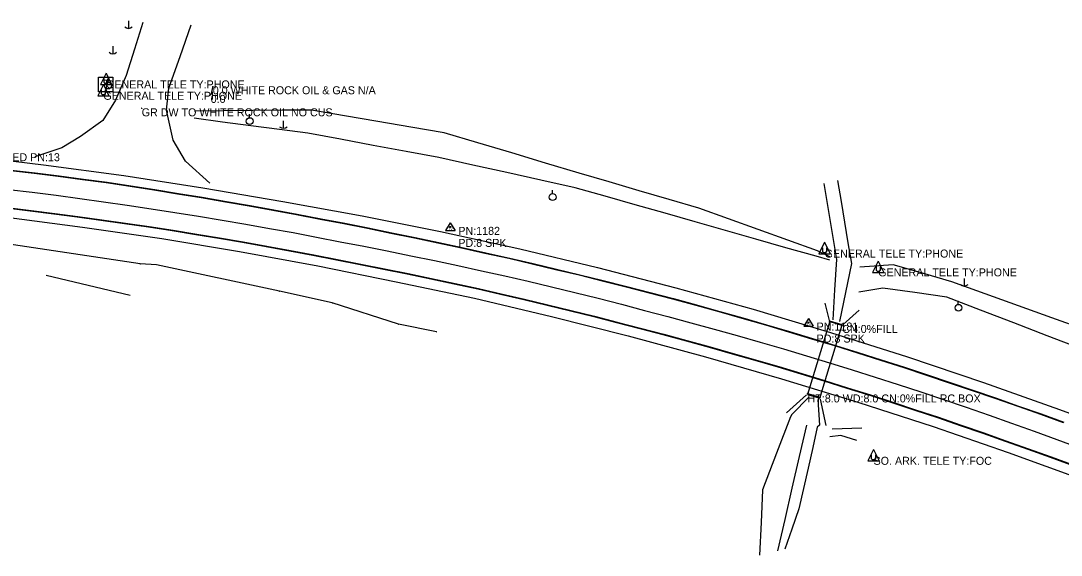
# Model space of a CAD drawing. Extents: x 878399 to 889864, y 1564003 to 1567413.
# Drawn here: x 882072 to 882722, y 1566924 to 1567257 of the extents above; entities that cross this region are included whole.
import ezdxf

# ---------------------------------------------------------------- set-up
doc = ezdxf.new("R2010")
doc.units = 0
for name, color, linetype in [('S_CROSS_DRAIN', 7, 'Continuous'), ('S_CROSS_DRAIN_ANNOT', 7, 'Continuous'), ('S_DITCHLINE', 7, 'Continuous'), ('S_DRG_PT_SYM', 7, 'Continuous'), ('S_DRIVEWAY', 7, 'Continuous'), ('S_EDGE_PAVEMENT', 7, 'Continuous'), ('S_FIBER_OPTIC_CABLE', 7, 'Continuous'), ('S_HEADWALL', 7, 'Continuous'), ('S_MSC_PT_SYM', 7, 'Continuous'), ('S_PAVEMENT_CROWN', 7, 'Continuous'), ('S_PRIMARY_CTL_ANNOT', 7, 'Continuous'), ('S_SECONDARY_CTL', 7, 'Continuous'), ('S_SECONDARY_CTL_ANNOT', 7, 'Continuous'), ('S_SHOULDER', 7, 'Continuous'), ('S_SIGN', 7, 'Continuous'), ('S_SIGN_ANNOT', 7, 'Continuous'), ('S_SURVEY_TEXT_ANNOT', 7, 'Continuous'), ('S_TELEPHONE_UTILITIES', 7, 'Continuous'), ('S_UTILITY_POLE', 7, 'Continuous'), ('S_UTILITY_POLE_ANNOT', 7, 'Continuous'), ('S_UTL_PT_SYM', 7, 'Continuous'), ('S_WALL', 7, 'Continuous')]:
    doc.layers.add(name, color=color, linetype=linetype)

msp = doc.modelspace()

# ---------------------------------------------------------------- linework, layer by layer
at = {"layer": 'S_CROSS_DRAIN'}
for p, q in [((882577.74, 1567069.92), (882563.77, 1567024.23)), ((882571.4, 1567021.9), (882585.44, 1567067.6)), ((882585.44, 1567067.6), (882577.74, 1567069.92)), ((882563.77, 1567024.23), (882571.4, 1567021.9))]:
    msp.add_line(p, q, dxfattribs=at)
at = {"layer": 'S_DITCHLINE'}
for points in [[(882577.64, 1567110.13), (882570.07, 1567113.96), (882551.53, 1567120.59), (882533, 1567127.23), (882514.46, 1567133.87), (882495.93, 1567140.5), (882477.24, 1567145.96), (882458.56, 1567151.41), (882439.87, 1567156.87), (882421.18, 1567162.33), (882400.06, 1567168.63), (882378.95, 1567174.94), (882357.83, 1567181.24), (882336.71, 1567187.55), (882315.99, 1567191.11), (882295.27, 1567194.66), (882274.55, 1567198.22), (882253.83, 1567201.78), (882235.56, 1567201.58), (882217.29, 1567201.38), (882199.02, 1567201.18), (882180.75, 1567200.98)], [(882577.71, 1567108.12), (882569.1, 1567110.44), (882550.22, 1567115.82), (882531.35, 1567121.2), (882512.47, 1567126.58), (882493.59, 1567131.96), (882474.82, 1567137.29), (882456.05, 1567142.63), (882437.28, 1567147.96), (882418.5, 1567153.29), (882397.24, 1567158), (882375.97, 1567162.7), (882354.71, 1567167.41), (882333.45, 1567172.12), (882312.98, 1567175.91), (882292.52, 1567179.71), (882272.05, 1567183.5), (882251.59, 1567187.29), (882233.85, 1567189.62), (882216.11, 1567191.95), (882198.38, 1567194.28), (882180.64, 1567196.61)], [(882579.77, 1567070.75), (882580.86, 1567089.59), (882581.95, 1567108.44), (882578.06, 1567132.14), (882574.17, 1567155.84)], [(882583.88, 1567069.68), (882587.64, 1567087.81), (882591.39, 1567105.93), (882589.21, 1567118.87), (882587.04, 1567131.82), (882584.86, 1567144.76), (882582.69, 1567157.7)], [(882737.26, 1567064.64), (882716.39, 1567072.13), (882695.52, 1567079.62), (882674.66, 1567087.11), (882653.79, 1567094.6), (882635.52, 1567099.84), (882617.25, 1567105.07), (882596.32, 1567103.69)], [(882140.71, 1567085.92), (882127.61, 1567089.06), (882114.5, 1567092.2), (882101.39, 1567095.34), (882088.28, 1567098.48)], [(882734.33, 1567052.82), (882713.46, 1567060.86), (882692.59, 1567068.89), (882671.72, 1567076.92), (882650.85, 1567084.95), (882630.79, 1567087.8), (882610.73, 1567090.64), (882595.71, 1567088.05)], [(882564.84, 1567022.71), (882553.84, 1567011.68), (882553.13, 1567010.32), (882544.37, 1566987.47), (882535.61, 1566964.61), (882534.7, 1566944.24), (882533.8, 1566923.88)], [(882570.18, 1567021.11), (882571.18, 1567005.13), (882569.84, 1567003.88), (882566.95, 1566991.09), (882564.06, 1566978.29), (882561.17, 1566965.5), (882558.28, 1566952.71), (882553.88, 1566940.2), (882549.48, 1566927.7)], [(882545.23, 1566926.51), (882549.73, 1566946.16), (882554.24, 1566965.81), (882558.75, 1566985.46), (882563.25, 1567005.12)], [(882597.6, 1567003.08), (882579.03, 1567002.61)], [(882594.52, 1566995.48), (882584.64, 1566998.54), (882577.69, 1566997.68)]]:
    msp.add_lwpolyline(points, dxfattribs=at)
at = {"layer": 'S_DRG_PT_SYM'}
for points in [[(882577.74, 1567069.92), (882577.74, 1567069.97), (882577.74, 1567069.92), (882577.69, 1567069.92), (882577.74, 1567069.92), (882577.74, 1567069.87), (882577.74, 1567069.92), (882577.79, 1567069.92)], [(882585.44, 1567067.6), (882585.44, 1567067.65), (882585.44, 1567067.6), (882585.39, 1567067.6), (882585.44, 1567067.6), (882585.44, 1567067.55), (882585.44, 1567067.6), (882585.49, 1567067.6)], [(882563.77, 1567024.23), (882563.77, 1567024.28), (882563.77, 1567024.23), (882563.72, 1567024.23), (882563.77, 1567024.23), (882563.77, 1567024.18), (882563.77, 1567024.23), (882563.82, 1567024.23)], [(882571.4, 1567021.9), (882571.4, 1567021.95), (882571.4, 1567021.9), (882571.35, 1567021.9), (882571.4, 1567021.9), (882571.4, 1567021.85), (882571.4, 1567021.9), (882571.45, 1567021.9)]]:
    msp.add_lwpolyline(points, dxfattribs=at)
at = {"layer": 'S_DRIVEWAY'}
for points in [[(882148.5, 1567256.43), (882143.36, 1567239.86), (882138.23, 1567223.29), (882131.55, 1567207.92), (882123.68, 1567195.31), (882109.64, 1567185.28), (882097.89, 1567178.24), (882081.07, 1567172.61)], [(882190.32, 1567156.11), (882175.28, 1567169.92), (882167.56, 1567182.95), (882163.27, 1567201.7), (882164.89, 1567215.46), (882171.82, 1567235.26), (882178.76, 1567255.05)]]:
    msp.add_lwpolyline(points, dxfattribs=at)
at = {"layer": 'S_EDGE_PAVEMENT'}
for points in [[(882065.86, 1567163.92), (882080.78, 1567162.37), (882080.78, 1567162.37), (882095.66, 1567160.52), (882110.88, 1567158.46), (882110.88, 1567158.46), (882125.75, 1567156.44), (882140.6, 1567154.31), (882140.6, 1567154.31), (882155.41, 1567151.91), (882170.22, 1567149.52), (882185.03, 1567147.12), (882185.03, 1567147.12), (882185.03, 1567147.12), (882200.21, 1567144.48), (882200.21, 1567144.48), (882214.99, 1567141.91), (882214.99, 1567141.91), (882214.99, 1567141.91), (882229.77, 1567139.33), (882229.77, 1567139.33), (882244.52, 1567136.58), (882259.39, 1567133.72), (882274.12, 1567130.88), (882274.12, 1567130.88), (882288.84, 1567127.97), (882288.84, 1567127.97), (882303.53, 1567124.94), (882318.22, 1567121.9), (882318.22, 1567121.9), (882318.22, 1567121.9), (882332.91, 1567118.86), (882332.91, 1567118.86), (882332.91, 1567118.86), (882347.57, 1567115.67), (882347.57, 1567115.67), (882362.23, 1567112.47), (882377.22, 1567109.2), (882377.22, 1567109.2), (882391.83, 1567105.79), (882391.83, 1567105.79), (882406.42, 1567102.29), (882421, 1567098.78), (882435.57, 1567095.2), (882435.57, 1567095.2), (882435.57, 1567095.2), (882450.38, 1567091.4), (882464.91, 1567087.67), (882479.45, 1567083.95), (882479.45, 1567083.95), (882479.45, 1567083.95), (882493.9, 1567079.92), (882508.35, 1567075.89), (882508.35, 1567075.89), (882508.35, 1567075.89), (882522.8, 1567071.85), (882522.8, 1567071.85), (882537.5, 1567067.57), (882551.88, 1567063.29), (882551.88, 1567063.29), (882566.25, 1567059.01), (882566.25, 1567059.01), (882566.25, 1567059.01), (882580.61, 1567054.67), (882594.93, 1567050.18), (882609.24, 1567045.69), (882623.85, 1567041.12), (882638.07, 1567036.34), (882652.28, 1567031.55), (882652.28, 1567031.55), (882666.5, 1567026.77), (882680.68, 1567021.86), (882695.03, 1567016.8), (882709.18, 1567011.82), (882723.31, 1567006.76)], [(882066.41, 1567164.12), (882081.33, 1567162.57), (882081.33, 1567162.57), (882096.22, 1567160.71), (882111.43, 1567158.65), (882111.43, 1567158.65), (882126.3, 1567156.64), (882141.15, 1567154.5), (882141.15, 1567154.5), (882155.96, 1567152.11), (882170.77, 1567149.71), (882185.58, 1567147.32), (882185.58, 1567147.32), (882185.58, 1567147.32), (882200.76, 1567144.68), (882200.76, 1567144.68), (882215.54, 1567142.1), (882215.54, 1567142.1), (882215.54, 1567142.1), (882230.32, 1567139.53), (882230.32, 1567139.53), (882245.06, 1567136.78), (882259.94, 1567133.91), (882274.67, 1567131.07), (882274.67, 1567131.07), (882289.38, 1567128.17), (882289.38, 1567128.17), (882304.07, 1567125.13), (882318.76, 1567122.1), (882318.76, 1567122.1), (882318.76, 1567122.1), (882333.45, 1567119.06), (882333.45, 1567119.06), (882333.45, 1567119.06), (882348.11, 1567115.86), (882348.11, 1567115.86), (882362.77, 1567112.67), (882377.76, 1567109.39), (882377.76, 1567109.39), (882392.37, 1567105.99), (882392.37, 1567105.99), (882406.96, 1567102.48), (882421.54, 1567098.98), (882436.11, 1567095.4), (882436.11, 1567095.4), (882436.11, 1567095.4), (882450.92, 1567091.6), (882465.45, 1567087.87), (882479.98, 1567084.14), (882479.98, 1567084.14), (882479.98, 1567084.14), (882494.43, 1567080.12), (882508.88, 1567076.09), (882508.88, 1567076.09), (882508.88, 1567076.09), (882523.33, 1567072.05), (882523.33, 1567072.05), (882538.03, 1567067.77), (882552.41, 1567063.49), (882552.41, 1567063.49), (882566.78, 1567059.21), (882566.78, 1567059.21), (882566.78, 1567059.21), (882581.14, 1567054.87), (882595.46, 1567050.38), (882609.77, 1567045.9), (882624.37, 1567041.32), (882638.59, 1567036.54), (882652.81, 1567031.76), (882652.81, 1567031.76), (882667.03, 1567026.97), (882681.2, 1567022.06), (882695.56, 1567017), (882709.71, 1567012.02), (882723.83, 1567006.96)], [(882063.3, 1567140.72), (882078.18, 1567138.83), (882093.06, 1567136.95), (882107.51, 1567135.12), (882122.37, 1567133.05), (882137.21, 1567130.92), (882137.21, 1567130.92), (882137.21, 1567130.92), (882152.06, 1567128.78), (882166.9, 1567126.53), (882181.7, 1567124.09), (882195.95, 1567121.74), (882210.75, 1567119.28), (882210.75, 1567119.28), (882225.51, 1567116.58), (882240.26, 1567113.87), (882254.84, 1567111.2), (882269.56, 1567108.32), (882284.27, 1567105.37), (882298.98, 1567102.42), (882298.98, 1567102.42), (882298.98, 1567102.42), (882313.68, 1567099.43), (882328.36, 1567096.36), (882343.04, 1567093.29), (882357.73, 1567090.21), (882371.89, 1567086.88), (882386.49, 1567083.45), (882401.1, 1567080.02), (882415.66, 1567076.44), (882415.66, 1567076.44), (882415.66, 1567076.44), (882430.21, 1567072.79), (882444.39, 1567069.23), (882458.92, 1567065.48), (882473.4, 1567061.56), (882487.88, 1567057.64), (882502.36, 1567053.71), (882516.77, 1567049.56), (882530.78, 1567045.52), (882545.2, 1567041.37), (882559.56, 1567037.04), (882573.9, 1567032.63), (882588.24, 1567028.23), (882602.55, 1567023.72), (882616.42, 1567019.16), (882630.67, 1567014.48), (882644.92, 1567009.79), (882659.1, 1567004.88), (882673.27, 1566999.97), (882687.17, 1566995.15), (882701.29, 1566990.09), (882715.39, 1566984.97), (882729.49, 1566979.85)], [(882063.85, 1567140.92), (882078.73, 1567139.03), (882093.62, 1567137.14), (882108.06, 1567135.31), (882122.92, 1567133.25), (882137.77, 1567131.11), (882137.77, 1567131.11), (882137.77, 1567131.11), (882152.61, 1567128.98), (882167.44, 1567126.73), (882182.25, 1567124.29), (882196.5, 1567121.94), (882211.3, 1567119.48), (882211.3, 1567119.48), (882226.06, 1567116.77), (882240.81, 1567114.07), (882255.38, 1567111.39), (882270.1, 1567108.51), (882284.81, 1567105.57), (882299.52, 1567102.62), (882299.52, 1567102.62), (882299.52, 1567102.62), (882314.22, 1567099.62), (882328.9, 1567096.56), (882343.59, 1567093.49), (882358.27, 1567090.41), (882372.43, 1567087.08), (882387.03, 1567083.65), (882401.63, 1567080.22), (882416.2, 1567076.64), (882416.2, 1567076.64), (882416.2, 1567076.64), (882430.75, 1567072.99), (882444.93, 1567069.43), (882459.45, 1567065.68), (882473.93, 1567061.76), (882488.41, 1567057.84), (882502.89, 1567053.91), (882517.31, 1567049.76), (882531.32, 1567045.72), (882545.73, 1567041.57), (882560.09, 1567037.24), (882574.43, 1567032.84), (882588.77, 1567028.43), (882603.08, 1567023.92), (882616.95, 1567019.37), (882631.2, 1567014.69), (882645.45, 1567009.99), (882659.62, 1567005.08), (882673.79, 1567000.17), (882687.7, 1566995.36), (882701.82, 1566990.3), (882715.92, 1566985.18), (882730.02, 1566980.06)]]:
    msp.add_lwpolyline(points, dxfattribs=at)
at = {"layer": 'S_FIBER_OPTIC_CABLE'}
for p, q in [((882146.98, 1567105.69), (882063.57, 1567118.17)), ((882157.14, 1567105.22), (882146.98, 1567105.69)), ((882233.84, 1567088.61), (882157.14, 1567105.22)), ((882266.92, 1567081.5), (882233.84, 1567088.61)), ((882308.36, 1567068.09), (882266.92, 1567081.5)), ((882332.06, 1567063.28), (882308.36, 1567068.09))]:
    msp.add_line(p, q, dxfattribs=at)
at = {"layer": 'S_HEADWALL'}
for points in [[(882585.82, 1567067.1), (882577.21, 1567069.77)], [(882572.05, 1567022.12), (882563.41, 1567024.82)]]:
    msp.add_lwpolyline(points, dxfattribs=at)
at = {"layer": 'S_MSC_PT_SYM'}
for points in [[(882190.96, 1567211.2), (882190.96, 1567211.25), (882190.96, 1567211.2), (882190.91, 1567211.2), (882190.96, 1567211.2), (882190.96, 1567211.15), (882190.96, 1567211.2), (882191.01, 1567211.2)], [(882192.25, 1567216.6), (882192.25, 1567216.65), (882192.25, 1567216.6), (882192.2, 1567216.6), (882192.25, 1567216.6), (882192.25, 1567216.55), (882192.25, 1567216.6), (882192.3, 1567216.6)], [(882147.86, 1567202.83), (882147.86, 1567202.88), (882147.86, 1567202.83), (882147.81, 1567202.83), (882147.86, 1567202.83), (882147.86, 1567202.78), (882147.86, 1567202.83), (882147.91, 1567202.83)]]:
    msp.add_lwpolyline(points, dxfattribs=at)
at = {"layer": 'S_PAVEMENT_CROWN'}
msp.add_lwpolyline([(882064.56, 1567152.19), (882079.46, 1567150.4), (882079.46, 1567150.4), (882079.46, 1567150.4), (882094.35, 1567148.56), (882094.35, 1567148.56), (882109.16, 1567146.54), (882124.02, 1567144.5), (882138.88, 1567142.46), (882153.71, 1567140.18), (882168.53, 1567137.84), (882183.35, 1567135.51), (882198.07, 1567133.06), (882212.85, 1567130.47), (882227.62, 1567127.88), (882227.62, 1567127.88), (882227.62, 1567127.88), (882242.39, 1567125.24), (882257.1, 1567122.4), (882271.83, 1567119.56), (882286.56, 1567116.71), (882301.27, 1567113.77), (882315.98, 1567110.81), (882330.68, 1567107.85), (882345.36, 1567104.73), (882360, 1567101.45), (882374.59, 1567098.18), (882389.22, 1567094.86), (882389.22, 1567094.86), (882389.22, 1567094.86), (882403.8, 1567091.33), (882418.38, 1567087.79), (882432.96, 1567084.26), (882447.44, 1567080.51), (882461.95, 1567076.71), (882476.46, 1567072.91), (882490.95, 1567068.99), (882505.4, 1567064.98), (882519.85, 1567060.96), (882534.25, 1567056.91), (882548.63, 1567052.62), (882563, 1567048.33), (882577.38, 1567044.04), (882591.69, 1567039.55), (882606, 1567035.03), (882620.26, 1567030.52), (882634.51, 1567025.84), (882648.72, 1567021.01), (882662.92, 1567016.18), (882677.11, 1567011.31), (882691.21, 1567006.27), (882705.34, 1567001.23), (882705.34, 1567001.23), (882705.34, 1567001.23), (882719.46, 1566996.18), (882733.53, 1566990.96)], dxfattribs=at)
at = {"layer": 'S_SECONDARY_CTL'}
for p, q in [((882340.63, 1567131.44), (882337.62, 1567126.48)), ((882337.62, 1567126.48), (882343.58, 1567126.48)), ((882340.63, 1567131.44), (882343.58, 1567126.48)), ((882564.41, 1567071.71), (882561.4, 1567066.75)), ((882564.41, 1567071.71), (882567.36, 1567066.75)), ((882561.4, 1567066.75), (882567.36, 1567066.75))]:
    msp.add_line(p, q, dxfattribs=at)
for centre, radius in [((882340.63, 1567128.83), 0.311), ((882340.63, 1567128.83), 0.183), ((882340.63, 1567128.83), 0.103), ((882564.41, 1567069.1), 0.311), ((882564.41, 1567069.1), 0.183), ((882564.41, 1567069.1), 0.103)]:
    msp.add_circle(centre, radius, dxfattribs=at)
at = {"layer": 'S_SHOULDER'}
for points in [[(882036.94, 1567173.62), (882086.58, 1567167.54), (882136.7, 1567160.92), (882186.12, 1567153.29), (882236.06, 1567144.69), (882285.5, 1567135.65), (882334.54, 1567125.88), (882383.98, 1567115.09), (882432.59, 1567103.36), (882481.51, 1567090.82), (882529.68, 1567077.38), (882578.11, 1567062.92), (882626.28, 1567047.69), (882673.65, 1567031.66), (882721.15, 1567014.88), (882768.55, 1566997.45)], [(882061.97, 1567134.99), (882110.92, 1567128.57), (882160.44, 1567121.62), (882208.96, 1567113.43), (882257.87, 1567104.45), (882306.86, 1567094.45), (882355.82, 1567084.25), (882403.84, 1567072.97), (882451.74, 1567060.71), (882500, 1567047.65), (882547.46, 1567033.99), (882595.26, 1567019.3), (882642.28, 1567004.13), (882689.13, 1566987.9), (882736.13, 1566970.85)]]:
    msp.add_lwpolyline(points, dxfattribs=at)
at = {"layer": 'S_SIGN'}
msp.add_line((882192.25, 1567216.6), (882190.96, 1567211.2), dxfattribs=at)
at = {"layer": 'S_TELEPHONE_UTILITIES'}
msp.add_lwpolyline([(882120.84, 1567213.22), (882120.84, 1567222.22), (882129.84, 1567222.22), (882129.84, 1567213.22)], close=True, dxfattribs=at)
at = {"layer": 'S_UTILITY_POLE'}
for p, q in [((882139.59, 1567257.45), (882139.59, 1567252.72)), ((882129.77, 1567241.62), (882129.77, 1567236.9)), ((882125.58, 1567224.8), (882122.05, 1567217.71)), ((882125.58, 1567224.8), (882129.06, 1567217.71)), ((882123.92, 1567217.7), (882120.39, 1567210.61)), ((882122.05, 1567217.71), (882129.06, 1567217.71)), ((882123.92, 1567217.7), (882127.4, 1567210.61)), ((882124.38, 1567218.95), (882124.38, 1567221.39)), ((882125, 1567218.29), (882124.38, 1567218.95)), ((882126.2, 1567218.29), (882125, 1567218.29)), ((882126.74, 1567218.95), (882126.2, 1567218.29)), ((882126.71, 1567219.17), (882126.71, 1567221.28)), ((882126.74, 1567221.39), (882126.74, 1567218.95)), ((882120.39, 1567210.61), (882127.4, 1567210.61)), ((882122.72, 1567211.85), (882122.72, 1567214.29)), ((882123.34, 1567211.19), (882122.72, 1567211.85)), ((882124.54, 1567211.19), (882123.34, 1567211.19)), ((882125.08, 1567211.85), (882124.54, 1567211.19)), ((882125.08, 1567214.29), (882125.08, 1567211.85)), ((882215.2, 1567197), (882215.2, 1567199.11)), ((882236.27, 1567195.07), (882236.27, 1567190.34)), ((882404.4, 1567149.59), (882404.4, 1567151.7)), ((882574.42, 1567119.18), (882570.89, 1567112.09)), ((882573.22, 1567113.33), (882573.22, 1567115.77)), ((882573.84, 1567112.67), (882573.22, 1567113.33)), ((882574.42, 1567119.18), (882577.91, 1567112.09)), ((882575.58, 1567113.33), (882575.04, 1567112.67)), ((882575.58, 1567115.77), (882575.58, 1567113.33)), ((882570.89, 1567112.09), (882577.91, 1567112.09)), ((882575.04, 1567112.67), (882573.84, 1567112.67)), ((882607.92, 1567107.47), (882604.4, 1567100.38)), ((882607.92, 1567107.47), (882611.41, 1567100.38)), ((882604.4, 1567100.38), (882611.41, 1567100.38)), ((882606.72, 1567101.62), (882606.72, 1567104.06)), ((882607.34, 1567100.96), (882606.72, 1567101.62)), ((882608.54, 1567100.96), (882607.34, 1567100.96)), ((882609.09, 1567101.62), (882608.54, 1567100.96)), ((882609.09, 1567104.06), (882609.09, 1567101.62)), ((882661.6, 1567096.6), (882661.6, 1567091.87)), ((882657.92, 1567080.44), (882657.92, 1567082.55)), ((882604.98, 1566989.84), (882601.45, 1566982.75)), ((882604.98, 1566989.84), (882608.47, 1566982.75)), ((882603.78, 1566983.99), (882603.78, 1566986.43)), ((882604.4, 1566983.33), (882603.78, 1566983.99)), ((882605.6, 1566983.33), (882604.4, 1566983.33)), ((882606.14, 1566983.99), (882605.6, 1566983.33)), ((882606.14, 1566986.43), (882606.14, 1566983.99)), ((882601.45, 1566982.75), (882608.47, 1566982.75))]:
    msp.add_line(p, q, dxfattribs=at)
for centre in [(882126.83, 1567217.03), (882215.33, 1567194.86), (882404.52, 1567147.45), (882658.04, 1567078.3)]:
    msp.add_circle(centre, 2.13, dxfattribs=at)
for centre in [(882139.65, 1567256.15), (882129.84, 1567240.32), (882236.33, 1567193.77), (882661.66, 1567095.3)]:
    msp.add_arc(centre, 3.41, 226.39718, 313.60282, dxfattribs=at)
at = {"layer": 'S_UTL_PT_SYM'}
for points in [[(882146.98, 1567105.69), (882146.98, 1567105.74), (882146.98, 1567105.69), (882146.93, 1567105.69), (882146.98, 1567105.69), (882146.98, 1567105.64), (882146.98, 1567105.69), (882147.03, 1567105.69)], [(882157.14, 1567105.22), (882157.14, 1567105.27), (882157.14, 1567105.22), (882157.09, 1567105.22), (882157.14, 1567105.22), (882157.14, 1567105.17), (882157.14, 1567105.22), (882157.19, 1567105.22)], [(882233.84, 1567088.61), (882233.84, 1567088.66), (882233.84, 1567088.61), (882233.79, 1567088.61), (882233.84, 1567088.61), (882233.84, 1567088.56), (882233.84, 1567088.61), (882233.89, 1567088.61)], [(882266.92, 1567081.5), (882266.92, 1567081.55), (882266.92, 1567081.5), (882266.87, 1567081.5), (882266.92, 1567081.5), (882266.92, 1567081.45), (882266.92, 1567081.5), (882266.97, 1567081.5)], [(882308.36, 1567068.09), (882308.36, 1567068.14), (882308.36, 1567068.09), (882308.31, 1567068.09), (882308.36, 1567068.09), (882308.36, 1567068.04), (882308.36, 1567068.09), (882308.41, 1567068.09)], [(882332.06, 1567063.28), (882332.06, 1567063.33), (882332.06, 1567063.28), (882332.01, 1567063.28), (882332.06, 1567063.28), (882332.06, 1567063.23), (882332.06, 1567063.28), (882332.11, 1567063.28)]]:
    msp.add_lwpolyline(points, dxfattribs=at)
at = {"layer": 'S_WALL'}
for points in [[(882577.48, 1567070.33), (882574.77, 1567081.28)], [(882585.99, 1567067.83), (882595.9, 1567076.75)], [(882563.17, 1567024.03), (882550.65, 1567012.64)], [(882575.44, 1567004.75), (882571.78, 1567021.31)]]:
    msp.add_lwpolyline(points, dxfattribs=at)

# ---------------------------------------------------------------- texts
at = {"layer": 'S_CROSS_DRAIN_ANNOT'}
for s, p in [('CN:0%FILL', (882585.44, 1567062.6)), ('HT:8.0 WD:8.0 CN:0%FILL RC BOX', (882563.77, 1567019.23))]:
    msp.add_text(s, height=5, dxfattribs=at).set_placement(p)
at = {"layer": 'S_PRIMARY_CTL_ANNOT'}
msp.add_text('PD:ARDOT STD. MON. STAMPED PN:13', height=5, dxfattribs=at).set_placement((881971.19, 1567169.81))
at = {"layer": 'S_SECONDARY_CTL'}
for p in [(882339.43, 1567126.82), (882563.21, 1567067.09)]:
    msp.add_text('TV', height=1.5, rotation=360, dxfattribs=at).set_placement(p)
at = {"layer": 'S_SECONDARY_CTL_ANNOT'}
for s, p in [('PN:1182', (882345.63, 1567123.83)), ('PD:8 SPK', (882345.63, 1567116.33)), ('PN:1181', (882569.41, 1567064.1)), ('PD:8 SPK', (882569.41, 1567056.6))]:
    msp.add_text(s, height=5, dxfattribs=at).set_placement(p)
at = {"layer": 'S_SIGN_ANNOT'}
for s, p in [('0.0', (882190.96, 1567206.2)), ('0.0 WHITE ROCK OIL & GAS N/A', (882192.25, 1567211.6))]:
    msp.add_text(s, height=5, dxfattribs=at).set_placement(p)
at = {"layer": 'S_SURVEY_TEXT_ANNOT'}
msp.add_text('GR DW TO WHITE ROCK OIL NO CUS', height=5, dxfattribs=at).set_placement((882147.86, 1567197.83))
at = {"layer": 'S_TELEPHONE_UTILITIES'}
msp.add_text('T', height=6, rotation=360, dxfattribs=at).set_placement((882123.4, 1567214.72))
at = {"layer": 'S_UTILITY_POLE_ANNOT'}
for s, p in [('GENERAL TELE TY:PHONE', (882125.58, 1567215.27)), ('GENERAL TELE TY:PHONE', (882123.92, 1567208.16)), ('GENERAL TELE TY:PHONE', (882574.42, 1567109.65)), ('GENERAL TELE TY:PHONE', (882607.92, 1567097.93)), ('SO. ARK. TELE TY:FOC', (882604.98, 1566980.3))]:
    msp.add_text(s, height=5, dxfattribs=at).set_placement(p)

doc.saveas('drawing.dxf')
